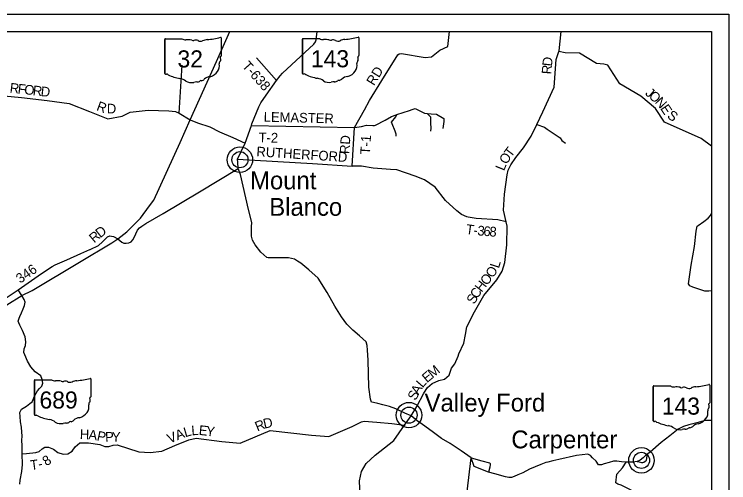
# Model space of a CAD drawing. Extents: x -84548 to 2262448, y -162180 to 525962.
# Drawn here: x -22558 to -515, y 152568 to 167016 of the extents above; entities that cross this region are included whole.
import ezdxf

# ---------------------------------------------------------------- set-up
doc = ezdxf.new("R2010")
doc.units = 0
for name, color, linetype in [('GM_X_Adjacent_County_Text', 7, 'Continuous'), ('GM_X_County', 7, 'Continuous'), ('GM_X_County_Road', 7, 'Continuous'), ('GM_X_Major_Lake_Text', 7, 'Continuous'), ('GM_X_Major_River', 7, 'Continuous'), ('GM_X_Major_River_Text', 7, 'Continuous'), ('GM_X_Minor_Lake', 7, 'Continuous'), ('GM_X_Minor_River_Text', 7, 'Continuous'), ('GM_X_Rail_Line', 7, 'Continuous'), ('GM_X_Township_Road', 7, 'Continuous'), ('GM_X_Township_Road_Text', 7, 'Continuous'), ('GM_X_Township_ROW', 7, 'Continuous')]:
    doc.layers.add(name, color=color, linetype=linetype)

msp = doc.modelspace()

# ---------------------------------------------------------------- linework, layer by layer
at = {"layer": 'GM_X_County'}
for p, q in [((-37475, 167016), (-515, 167016)), ((-515, 167016), (-515, 130056)), ((-36947, 166488), (-1043, 166488)), ((-36947, 166488), (-1043, 166488)), ((-1043, 166488), (-1043, 130584)), ((-1043, 166488), (-1043, 130584))]:
    msp.add_line(p, q, dxfattribs=at)
at = {"layer": 'GM_X_Major_Lake_Text'}
for points in [[(-18382, 161104), (-18251, 161281), (-17443, 163066), (-17130, 163762), (-16322, 165562), (-15905, 166488)], [(-22327, 158342), (-22011, 158497), (-20548, 159373), (-19544, 159966), (-19367, 160095), (-19085, 160302), (-18663, 160725), (-18382, 161104)], [(-28900, 155108), (-27464, 155206), (-27302, 155226), (-26739, 155297), (-26369, 155408), (-26075, 155559), (-25841, 155735), (-25407, 156103), (-24466, 156932), (-24098, 157219), (-23724, 157483), (-22327, 158342)], [(-22387, 157697), (-22387, 157697), (-22338, 157806), (-22283, 157929), (-22244, 158036), (-22227, 158138), (-22250, 158218), (-22327, 158342)], [(-22382, 152522), (-22375, 152644), (-22320, 152913), (-22305, 153126), (-22315, 153454), (-22319, 153711), (-22327, 153867), (-22317, 154012), (-22322, 154130), (-22336, 154282), (-22362, 154442), (-22374, 154609), (-22386, 154731), (-22339, 154834), (-22183, 154932), (-22080, 155009), (-22005, 155066), (-21919, 155261), (-21842, 155399), (-21783, 155477), (-21710, 155546), (-21682, 155635), (-21694, 155751), (-21743, 155867), (-21915, 155987), (-22045, 156140), (-22152, 156319), (-22230, 156513), (-22261, 156588), (-22248, 156693), (-22213, 156795), (-22197, 156914), (-22221, 157066), (-22307, 157267), (-22389, 157425), (-22420, 157495), (-22439, 157554), (-22412, 157643), (-22387, 157697)], [(-1043, 154488), (-1059, 154488), (-1239, 154482), (-1494, 154416), (-1749, 154355), (-1911, 154297), (-2076, 154221), (-2336, 154013), (-2599, 153806), (-2939, 153510), (-3012, 153459), (-3063, 153424), (-3149, 153340), (-3244, 153264), (-3334, 153217), (-3470, 153198), (-3555, 153198), (-3682, 153203), (-3821, 153207), (-3964, 153231), (-4074, 153229), (-4198, 153187), (-4355, 153145), (-4443, 153123), (-4531, 153121), (-4603, 153228), (-4716, 153340), (-4776, 153412), (-4864, 153453), (-5209, 153409), (-5758, 153280), (-5943, 153238), (-6096, 153205)], [(-6096, 153205), (-6096, 153205), (-6159, 153192), (-6312, 153130), (-6657, 152982), (-6868, 152874), (-7018, 152806), (-7136, 152762), (-7217, 152730), (-7267, 152726), (-7298, 152730)]]:
    msp.add_lwpolyline(points, dxfattribs=at)
at = {"layer": 'GM_X_Major_River'}
for centre, radius in [((-15596, 162530), 393), ((-15596, 162530), 249), ((-10380, 154652), 393), ((-10380, 154652), 249), ((-3207, 153257), 393), ((-3207, 153257), 249)]:
    msp.add_circle(centre, radius, dxfattribs=at)
at = {"layer": 'GM_X_Major_River_Text'}
msp.add_lwpolyline([(-7298, 152730), (-7298, 152730), (-7403, 152745), (-7728, 152843), (-7926, 152893), (-8373, 153073), (-8460, 153340), (-8768, 153555), (-9110, 153775), (-9372, 153931), (-9668, 154146), (-9961, 154365), (-10123, 154477), (-10313, 154626), (-10510, 154713), (-10785, 154849), (-10982, 154916), (-11187, 154972), (-11340, 155009), (-11471, 155039), (-11539, 155056), (-11566, 155148), (-11615, 155519), (-11642, 156344), (-11656, 156657), (-11668, 156799), (-11703, 156917), (-11906, 157101), (-12114, 157271), (-12295, 157459), (-12458, 157680), (-12670, 158010), (-12900, 158432), (-13178, 158874), (-13471, 159137), (-13720, 159341), (-13815, 159406), (-13914, 159467), (-14097, 159499), (-14386, 159499), (-14598, 159499), (-14723, 159507), (-14769, 159517), (-14947, 159675), (-15124, 159906), (-15206, 160053), (-15240, 160175), (-15242, 160379), (-15243, 160465), (-15232, 160591), (-15336, 160995), (-15573, 162077), (-15648, 162264), (-15657, 162453), (-15670, 162547), (-15432, 163041), (-15241, 163590), (-15226, 163634), (-15015, 164158), (-14949, 164286), (-14785, 164521), (-14463, 164969), (-14353, 165122), (-14283, 165201), (-13311, 166098), (-13263, 166164), (-13243, 166227), (-13211, 166488)], dxfattribs=at)
at = {"layer": 'GM_X_Minor_Lake'}
for points in [[(-12058, 163521), (-11747, 164068), (-11594, 164352), (-11216, 164976), (-10724, 165764), (-10680, 165797), (-10608, 165803), (-9881, 165684), (-9681, 165705), (-9424, 165907), (-9183, 166018), (-9129, 166488)], [(-1043, 162951), (-1365, 163189), (-2500, 163689), (-2774, 164114), (-3225, 164492), (-3878, 164869), (-4245, 165446), (-4370, 165479), (-4589, 165495), (-5116, 165813), (-5562, 165824), (-5752, 165873)], [(-14463, 164969), (-15087, 165670)], [(-17466, 163971), (-17373, 165445)], [(-22865, 164505), (-22333, 164453), (-21545, 164355), (-20863, 164262), (-20238, 164013), (-19672, 163791), (-19229, 163872), (-18986, 164000), (-18425, 164063), (-17785, 164039), (-17581, 164013), (-17466, 163971)], [(-17466, 163971), (-17130, 163762)], [(-17130, 163762), (-16907, 163667), (-16524, 163548), (-16223, 163391), (-15816, 163215), (-15432, 163041)], [(-15241, 163590), (-12058, 163521)], [(-15670, 162547), (-13353, 162409), (-12130, 162330), (-12058, 163521)], [(-10950, 162228), (-11481, 162269), (-11847, 162331), (-12130, 162330)], [(-7380, 160616), (-7643, 160671), (-8302, 160722), (-8556, 160758)], [(-1043, 158491), (-1125, 158474), (-1249, 158478), (-1626, 158594), (-1712, 158637), (-1759, 158701), (-1677, 159281), (-1565, 159858), (-1520, 160331), (-1500, 160433), (-1485, 160476), (-1462, 160506), (-1277, 160628), (-1153, 160732), (-1080, 160811), (-1043, 160859)], [(-22315, 153454), (-22176, 153468), (-21890, 153502), (-21791, 153532), (-21695, 153616), (-21613, 153664), (-21501, 153661), (-21350, 153604), (-21218, 153498), (-21047, 153444), (-20907, 153456), (-20775, 153541), (-20683, 153679), (-20540, 153799), (-20272, 153798), (-19919, 153746), (-19764, 153684), (-19640, 153684), (-19508, 153724), (-19385, 153738), (-18717, 153520), (-18367, 153500), (-18008, 153536), (-17609, 153715), (-17174, 153888), (-16951, 153942), (-16149, 153838), (-15588, 153786), (-14667, 154182), (-13390, 154036), (-12851, 153996), (-12129, 154306), (-11841, 154448), (-11759, 154466), (-11369, 154439), (-10913, 154394), (-10514, 154342), (-10501, 154341)], [(-5811, 143673), (-5986, 143670), (-6466, 143708), (-6723, 143828), (-7259, 144208), (-7444, 144866), (-7474, 145367), (-7437, 145648), (-7510, 146098), (-7628, 146257), (-7740, 146362), (-7751, 146404), (-7788, 146542), (-7659, 146864), (-7558, 147481), (-7490, 147878), (-7576, 148601), (-7833, 148829), (-8295, 149164), (-8357, 149358), (-8361, 150463), (-8709, 151260), (-8460, 153340)], [(-8460, 153340), (-8127, 153244), (-7897, 153176), (-7871, 153157), (-7871, 153130), (-7888, 153046), (-7926, 152893)]]:
    msp.add_lwpolyline(points, dxfattribs=at)
at = {"layer": 'GM_X_Minor_River_Text'}
for points in [[(-10313, 154626), (-10133, 154921), (-9918, 155329), (-9808, 155509), (-9668, 155628), (-9456, 155717), (-9286, 155764), (-9136, 155887), (-9063, 156100), (-8969, 156233), (-8865, 156476), (-8844, 156544), (-8689, 156867), (-8634, 157144), (-8597, 157371), (-8356, 157843), (-8068, 158347), (-7669, 158826), (-7507, 159095), (-7423, 159355), (-7358, 159903), (-7347, 160476), (-7380, 160616), (-7465, 160976), (-7433, 161469), (-7349, 162064), (-7320, 162203), (-7239, 162371), (-7079, 162595), (-6842, 162900), (-6606, 163252), (-6436, 163613), (-6250, 164007), (-5905, 164766), (-5840, 165623), (-5752, 165873), (-5747, 165888), (-5689, 166488)], [(-18497, 160558), (-18495, 160559), (-17964, 160873), (-16846, 161535), (-15648, 162264)], [(-20220, 159766), (-19957, 159884), (-19832, 160002), (-19746, 160088), (-19681, 160147), (-19614, 160179), (-19556, 160177), (-19498, 160163), (-19367, 160095), (-19235, 159984), (-19174, 159960), (-19104, 159954), (-19022, 159966), (-18952, 159996), (-18898, 160059), (-18858, 160133), (-18756, 160361), (-18696, 160431), (-18621, 160484), (-18497, 160558)], [(-21822, 158947), (-21474, 159187), (-21390, 159241), (-21292, 159291), (-20941, 159444), (-20504, 159641), (-20223, 159765), (-20220, 159766)], [(-24178, 157521), (-24173, 157523), (-23434, 157860), (-22440, 158520), (-21822, 158947)], [(-22327, 158342), (-22440, 158520)], [(-11874, 151931), (-11904, 152622), (-11847, 152909), (-11697, 153158), (-11422, 153420), (-10846, 153873), (-10514, 154342), (-10313, 154626)], [(-1903, 149479), (-1934, 149642), (-1977, 149864), (-2048, 150076), (-2216, 150484), (-2279, 150642), (-2370, 150790), (-2622, 151077), (-2767, 151261), (-2870, 151515), (-3016, 151747), (-3216, 152042), (-3528, 152337), (-3835, 152492), (-3934, 152522), (-4002, 152565), (-3971, 152834), (-3795, 153025), (-3682, 153203)]]:
    msp.add_lwpolyline(points, dxfattribs=at)
at = {"layer": 'GM_X_Rail_Line'}
for p, q in [((-17912, 166243), (-17912, 165187)), ((-17912, 165187), (-17912, 166243)), ((-17912, 165187), (-17912, 166243)), ((-17895, 166261), (-17386, 166261)), ((-16172, 166288), (-16172, 165735)), ((-13668, 166249), (-13668, 165192)), ((-13668, 165192), (-13668, 166249)), ((-13668, 165192), (-13668, 166249)), ((-13650, 166267), (-13141, 166267)), ((-11927, 166293), (-11927, 165740)), ((-16172, 165735), (-16172, 165735)), ((-11927, 165741), (-11927, 165740)), ((-21939, 155724), (-21939, 154667)), ((-21939, 154667), (-21939, 155724)), ((-21939, 154667), (-21939, 155724)), ((-21922, 155742), (-21413, 155742)), ((-20199, 155768), (-20199, 155216)), ((-2842, 155535), (-2842, 154479)), ((-2842, 154479), (-2842, 155535)), ((-2842, 154479), (-2842, 155535)), ((-2824, 155554), (-2315, 155554)), ((-1101, 155580), (-1101, 155027)), ((-20199, 155216), (-20199, 155216)), ((-1102, 155027), (-1101, 155027))]:
    msp.add_line(p, q, dxfattribs=at)
for centre, major_axis, start_param, end_param in [((-17892, 166246), (20.2, 0), 1.712693, 3.28349), ((-17264, 166384), (196, 0), 4.042523, 4.731795), ((-17199, 165668), (702, 0), 1.404758, 1.657858), ((-17040, 166251), (56.4, 0), 3.836095, 5.185415), ((-16957, 166129), (117, 0), 0.950623, 2.079405), ((-16557, 165939), (371, 0), 1.699011, 2.107814), ((-16792, 167702), (1845, 0), 4.814394, 5.042369), ((-16192, 166290), (19.4, 0), 6.141152, 7.989035), ((-13648, 166251), (20.2, 0), 1.712693, 3.28349), ((-13019, 166390), (196, 0), 4.042523, 4.731795), ((-12955, 165674), (702, 0), 1.404758, 1.657858), ((-12795, 166257), (56.4, 0), 3.836095, 5.185415), ((-12712, 166134), (117, 0), 0.950623, 2.079405), ((-12561, 166302), (141, 0), 4.081561, 5.145723), ((-12312, 165944), (371, 0), 1.699011, 2.107814), ((-12547, 167708), (1845, 0), 4.814394, 5.042369), ((-11947, 166296), (19.4, 0), 6.141152, 7.989035), ((-16806, 166296), (141, 0), 4.081561, 5.145723), ((-16103, 165504), (131, 0), 2.387724, 3.262537), ((-16177, 165694), (30, 0), 1.883978, 3.671073), ((-16367, 165624), (180, 0), 5.934695, 6.695948), ((-16193, 165733), (20.7, 0), 5.05454, 6.418171), ((-11858, 165509), (131, 0), 2.387724, 3.262537), ((-11932, 165700), (30, 0), 1.883978, 3.671073), ((-12123, 165630), (180, 0), 5.934695, 6.695948), ((-11948, 165738), (20.7, 0), 5.05454, 6.418171), ((-16689, 165433), (462, 0), 5.101752, 6.440018), ((-12444, 165439), (462, 0), 5.101752, 6.440018), ((-17892, 165184), (20.3, 0), 3.00124, 4.508301), ((-17889, 165292), (155, 0), 4.665946, 4.897461), ((-17857, 165126), (56, 0), 0.519207, 1.627899), ((-17151, 166075), (1333, 0), 4.195997, 4.488961), ((-13647, 165190), (20.3, 0), 3.00124, 4.508301), ((-13644, 165298), (155, 0), 4.665946, 4.897461), ((-13613, 165131), (56, 0), 0.519207, 1.627899), ((-12906, 166081), (1333, 0), 4.195997, 4.488961), ((-17548, 164712), (417, 0), 0.823519, 1.323587), ((-17097, 165120), (265, 0), 4.026481, 4.996735), ((-16944, 164755), (217, 0), 1.495662, 1.94098), ((-16925, 165041), (141, 0), 4.691044, 5.507374), ((-16797, 164939), (39.7, 0), 1.147584, 2.315152), ((-16814, 165084), (149, 0), 4.937069, 5.64225), ((-16494, 164890), (253, 0), 1.647645, 2.488434), ((-13303, 164718), (417, 0), 0.823519, 1.323587), ((-12852, 165126), (265, 0), 4.026481, 4.996735), ((-12699, 164761), (217, 0), 1.495662, 1.94098), ((-12680, 165047), (141, 0), 4.691044, 5.507374), ((-12553, 164945), (39.7, 0), 1.147584, 2.315152), ((-12569, 165090), (149, 0), 4.937069, 5.64225), ((-12249, 164896), (253, 0), 1.647645, 2.488434), ((-21919, 155726), (20.2, 0), 1.712693, 3.28349), ((-21291, 155865), (196, 0), 4.042523, 4.731795), ((-21226, 155149), (702, 0), 1.404758, 1.657858), ((-21067, 155732), (56.4, 0), 3.836095, 5.185415), ((-20984, 155610), (117, 0), 0.950623, 2.079405), ((-20833, 155777), (141, 0), 4.081561, 5.145723), ((-20584, 155419), (371, 0), 1.699011, 2.107814), ((-20819, 157183), (1845, 0), 4.814394, 5.042369), ((-20218, 155771), (19.4, 0), 6.141152, 7.989035), ((-2822, 155538), (20.2, 0), 1.712693, 3.28349), ((-2193, 155676), (196, 0), 4.042523, 4.731795), ((-2129, 154960), (702, 0), 1.404758, 1.657858), ((-1969, 155543), (56.4, 0), 3.836095, 5.185415), ((-1886, 155421), (117, 0), 0.950623, 2.079405), ((-1735, 155588), (141, 0), 4.081561, 5.145723), ((-1486, 155231), (371, 0), 1.699011, 2.107814), ((-1721, 156994), (1845, 0), 4.814394, 5.042369), ((-1121, 155582), (19.4, 0), 6.141152, 7.989035), ((-20204, 155175), (30, 0), 1.883978, 3.671073), ((-20220, 155213), (20.7, 0), 5.05454, 6.418171), ((-20716, 154914), (462, 0), 5.101752, 6.440018), ((-20130, 154984), (131, 0), 2.387724, 3.262537), ((-20394, 155105), (180, 0), 5.934695, 6.695948), ((-1106, 154986), (30, 0), 1.883978, 3.671073), ((-1297, 154917), (180, 0), 5.934695, 6.695948), ((-1122, 155025), (20.7, 0), 5.05454, 6.418171), ((-1618, 154725), (462, 0), 5.101752, 6.440018), ((-1032, 154796), (131, 0), 2.387724, 3.262537), ((-21919, 154665), (20.3, 0), 3.00124, 4.508301), ((-21916, 154773), (155, 0), 4.665946, 4.897461), ((-21884, 154606), (56, 0), 0.519207, 1.627899), ((-21178, 155556), (1333, 0), 4.195997, 4.488961), ((-20521, 154371), (253, 0), 1.647645, 2.488434), ((-21575, 154193), (417, 0), 0.823519, 1.323587), ((-21124, 154601), (265, 0), 4.026481, 4.996735), ((-20971, 154236), (217, 0), 1.495662, 1.94098), ((-20952, 154522), (141, 0), 4.691044, 5.507374), ((-20824, 154420), (39.7, 0), 1.147584, 2.315152), ((-20841, 154565), (149, 0), 4.937069, 5.64225), ((-2821, 154476), (20.3, 0), 3.00124, 4.508301), ((-2818, 154584), (155, 0), 4.665946, 4.897461), ((-2787, 154418), (56, 0), 0.519207, 1.627899), ((-2080, 155367), (1333, 0), 4.195997, 4.488961), ((-2477, 154004), (417, 0), 0.823519, 1.323587), ((-1744, 154376), (149, 0), 4.937069, 5.64225), ((-1423, 154182), (253, 0), 1.647645, 2.488434), ((-2026, 154412), (265, 0), 4.026481, 4.996735), ((-1873, 154047), (217, 0), 1.495662, 1.94098), ((-1854, 154333), (141, 0), 4.691044, 5.507374), ((-1727, 154231), (39.7, 0), 1.147584, 2.315152)]:
    msp.add_ellipse(centre, major_axis=major_axis, ratio=0.8, start_param=start_param, end_param=end_param, dxfattribs=at)
at = {"layer": 'GM_X_Township_Road_Text'}
for points in [[(-8556, 160758), (-8558, 160759), (-8597, 160764), (-8761, 160837), (-8902, 160955), (-9253, 161272), (-9570, 161683), (-9906, 161908), (-10184, 162027), (-10752, 162213), (-10949, 162228), (-10950, 162228)], [(-3094, 153233), (-3093, 153233), (-3056, 153258), (-3038, 153328), (-3026, 153400), (-3012, 153459)]]:
    msp.add_lwpolyline(points, dxfattribs=at)
at = {"layer": 'GM_X_Township_ROW'}
for points in [[(-10778, 163913), (-10752, 163921), (-10363, 164048), (-10281, 164074), (-10186, 164105), (-9902, 163967), (-9894, 163966)], [(-12058, 163521), (-11849, 163558), (-11687, 163598), (-11492, 163581), (-11445, 163590), (-11411, 163597), (-11118, 163753), (-10921, 163866), (-10778, 163913)], [(-10774, 163256), (-10776, 163318), (-10803, 163411), (-10900, 163642), (-10920, 163688), (-10781, 163853), (-10752, 163921)], [(-9894, 163966), (-9814, 163959), (-9695, 163949), (-9531, 163934), (-9300, 163806), (-9302, 163705), (-9332, 163490)], [(-9704, 163408), (-9702, 163427), (-9698, 163479), (-9701, 163675), (-9701, 163761), (-9701, 163838), (-9814, 163959)], [(-6436, 163613), (-6195, 163535), (-6113, 163475), (-5713, 163203), (-5665, 163123), (-5553, 163043)], [(-3334, 153217), (-3282, 153210), (-3208, 153192), (-3185, 153193)], [(-3185, 153193), (-3185, 153193), (-3168, 153194), (-3136, 153206), (-3094, 153233)]]:
    msp.add_lwpolyline(points, dxfattribs=at)

# ---------------------------------------------------------------- texts
at = {"layer": 'GM_X_Adjacent_County_Text'}
for s, p in [('Mount', (-15282, 161617)), ('Blanco', (-14690, 160801)), ('Valley Ford', (-9897, 154762)), ('Carpenter', (-7222, 153628))]:
    msp.add_text(s, height=550, rotation=0, dxfattribs=at).set_placement(p)
at = {"layer": 'GM_X_County_Road'}
for s, rotation, p in [('D', 84.1836, (-5970, 165400)), ('R', 85.7575, (-5988, 165157)), ('T', 53.0967, (-7230, 162581)), ('O', 57.1505, (-7370, 162364)), ('L', 68.1683, (-7447, 162169)), ('R', 40.1369, (-20094, 159947)), ('D', 37.9657, (-19908, 160104)), ('L', 72.2732, (-7609, 159164)), ('346', 34.5788, (-22377, 158704)), ('O', 56.8922, (-7791, 158864)), ('O', 50.8264, (-7978, 158631)), ('H', 52.0212, (-8139, 158425)), ('C', 57.451, (-8268, 158223)), ('S', 59.997, (-8367, 158051)), ('M', 38.89, (-9653, 155779)), ('E', 39.6316, (-9825, 155636)), ('L', 49.1156, (-9963, 155476)), ('S', 62.0452, (-10177, 155082)), ('A', 60.5389, (-10083, 155259))]:
    msp.add_text(s, height=300, rotation=rotation, dxfattribs=at).set_placement(p)
at = {"layer": 'GM_X_Rail_Line'}
for s, p in [('32', (-17522, 165375)), ('143', (-13406, 165381)), ('689', (-21780, 154856)), ('143', (-2580, 154667))]:
    msp.add_text(s, height=528, dxfattribs=at).set_placement(p)
at = {"layer": 'GM_X_Township_Road'}
for s, rotation, p in [('T-638', 311.6339, (-15547, 165410)), ('RD', 58.359, (-11459, 164793)), ('R', 353.2962, (-22710, 164605)), ('F', 353.5539, (-22463, 164576)), ('O', 353.5532, (-22262, 164553)), ('R', 353.5503, (-22000, 164524)), ('D', 353.5533, (-21755, 164496)), ('J', 319.9566, (-3112, 164549)), ('O', 319.5872, (-3005, 164459)), ('N', 313.1889, (-2810, 164294)), ('R', 339.8665, (-20043, 164062)), ('D', 359.4807, (-19703, 163957)), ('E', 303.3656, (-2638, 164112)), ('LEMASTER', 358.5677, (-14865, 163705)), ('S', 323.1327, (-2437, 163843)), ('T-2', 358.5669, (-15022, 163070)), ('RD', 86.5467, (-12219, 162700)), ('T-1', 86.6615, (-11585, 162685)), ('RUTHERFORD', 356.3915, (-15094, 162636)), ('T', 351.9899, (-8640, 160247)), ('3', 354.8519, (-8279, 160201)), ('6', 355.471, (-8092, 160184)), ('-', 354.1681, (-8406, 160214)), ('8', 355.6151, (-7907, 160170)), ('D', 12.8947, (-14842, 154233)), ('L', 4.0618, (-17085, 154028)), ('E', 354.1014, (-16875, 154044)), ('Y', 353.1425, (-16653, 154021)), ('R', 22.2935, (-15057, 154144)), ('H', 358.2293, (-20539, 153915)), ('A', 353.414, (-20281, 153907)), ('P', 347.6846, (-20027, 153878)), ('P', 1.5322, (-19751, 153828)), ('Y', 358.7723, (-19552, 153833)), ('V', 22.9345, (-17764, 153772)), ('A', 21.3056, (-17523, 153874)), ('L', 16.4369, (-17284, 153968)), ('T', 7.5907, (-22047, 152958)), ('8', 33.7197, (-21567, 153070)), ('-', 14.0358, (-21789, 152995))]:
    msp.add_text(s, height=300, rotation=rotation, dxfattribs=at).set_placement(p)

doc.saveas('drawing.dxf')
